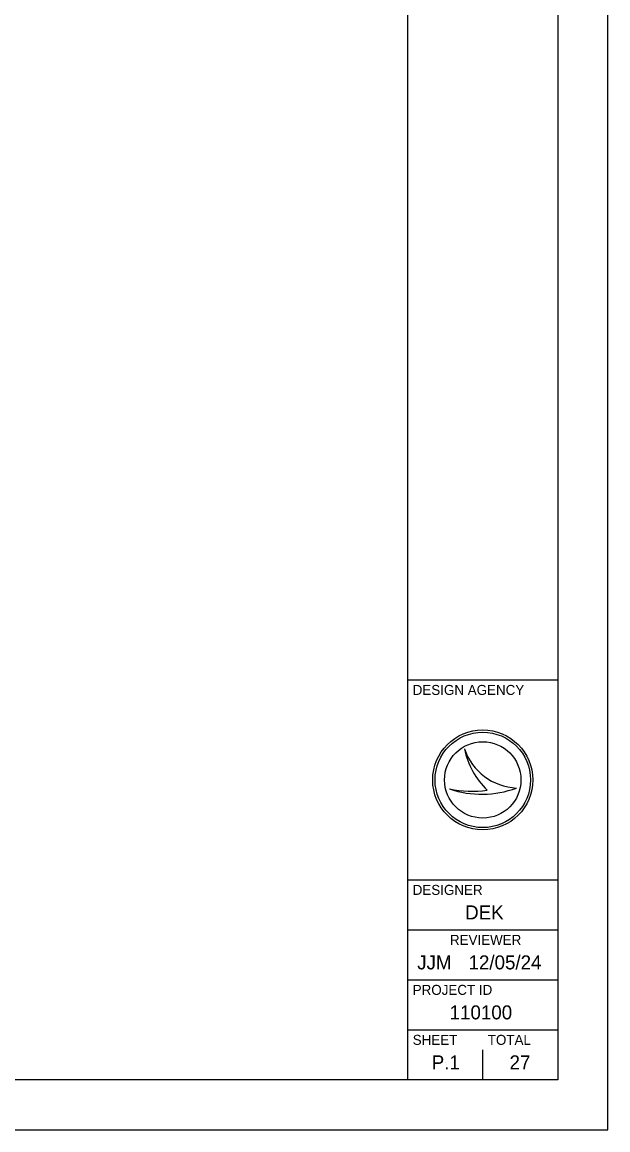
# Model space of a CAD drawing. Extents: x 0 to 34, y 0 to 22.
# Drawn here: x 28.15 to 34, y 0 to 11.08 of the extents above; entities that cross this region are included whole.
import ezdxf

# ---------------------------------------------------------------- set-up
doc = ezdxf.new("R2010")
doc.units = 0
for name, color, linetype in [('SH_Border', 7, 'Continuous'), ('SH_Cut_Line', 7, 'Continuous'), ('SH_Data', 7, 'Continuous')]:
    doc.layers.add(name, color=color, linetype=linetype)

msp = doc.modelspace()

# ---------------------------------------------------------------- linework, layer by layer
at = {"layer": 'SH_Border'}
for p, q in [((32, 0.5), (32, 21.5)), ((32, 4.5), (33.5, 4.5)), ((32, 2.5), (33.5, 2.5)), ((32, 2), (33.5, 2)), ((32, 1.5), (33.5, 1.5)), ((32, 1), (33.5, 1))]:
    msp.add_line(p, q, dxfattribs=at)
msp.add_lwpolyline([(1.5, 21.5), (33.5, 21.5), (33.5, 0.5), (1.5, 0.5)], close=True, dxfattribs=at)
at = {"layer": 'SH_Cut_Line'}
msp.add_lwpolyline([(0, 0), (34, 0), (34, 22), (0, 22)], close=True, dxfattribs=at)
at = {"layer": 'SH_Data'}
for p, q in [((32.567, 3.81), (32.567, 3.81)), ((32.75, 3.5), (32.75, 3.5)), ((32.417, 3.41), (32.417, 3.41)), ((33.087, 3.419), (33.087, 3.419)), ((32.75, 0.5), (32.75, 0.8)), ((32.375, 0.675), (32.375, 0.675))]:
    msp.add_line(p, q, dxfattribs=at)
for radius in [0.5, 0.477, 0.477, 0.382]:
    msp.add_circle((32.75, 3.5), radius, dxfattribs=at)
for centre, radius, start, end in [((33.116, 3.998), 0.58, 198.9257, 198.9319), ((33.347, 3.97), 0.796, 191.6379, 191.6421), ((33.116, 3.998), 0.58, 198.9319, 267.1657), ((33.347, 3.97), 0.796, 191.6421, 226.0947), ((32.739, 4.37), 1.013, 251.4576, 290.0832), ((32.648, 4.654), 1.266, 259.4964, 259.4995), ((32.739, 4.37), 1.013, 251.4527, 251.4576), ((32.648, 4.654), 1.266, 259.4995, 276.6672)]:
    msp.add_arc(centre, radius, start, end, dxfattribs=at)

# ---------------------------------------------------------------- texts
for s, height, p in [('DESIGN AGENCY', 0.1, (32.05, 4.35)), ('DESIGNER', 0.1, (32.05, 2.35)), ('DEK', 0.14, (32.574, 2.105)), ('REVIEWER', 0.1, (32.422, 1.85)), ('JJM', 0.14, (32.095, 1.605)), ('12/05/24', 0.14, (32.608, 1.605)), ('PROJECT ID', 0.1, (32.05, 1.35)), ('110100', 0.14, (32.419, 1.105)), ('SHEET', 0.1, (32.05, 0.85)), ('TOTAL', 0.1, (32.8, 0.85)), ('P.1', 0.14, (32.24, 0.605)), ('27', 0.14, (33.018, 0.605))]:
    msp.add_text(s, height=height, dxfattribs=at).set_placement(p)

doc.saveas('drawing.dxf')
